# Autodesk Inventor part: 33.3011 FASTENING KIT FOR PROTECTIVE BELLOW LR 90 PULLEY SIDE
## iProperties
Created: 2007-06
Part Number: 33.3011 FASTENING KIT FOR PROTECTIVE BELLOW LR 90 PULLEY SIDE
Document SubType Name: Modeling
Designer: Andy Moles
Material: Aluminum-6061
Mass: 99.325 g
Surface Area: 277.465 cm^2
Volume: 36.6513 cm^3
Density: 2.71 g/cm^3
Author: Andy Moles
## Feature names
1. Extrusion1
2. Hole1
3. Hole2
